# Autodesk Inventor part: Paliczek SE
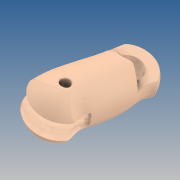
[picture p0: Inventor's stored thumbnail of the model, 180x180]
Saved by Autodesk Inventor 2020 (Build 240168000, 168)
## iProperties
Created: 2019-10
Part Number: Paliczek SE
Material: GFRP
Document SubType Name: Modeling
Designer: yello
Density: 1.75 g/cm^3
Appearance: Default
Author: yello
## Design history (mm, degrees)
feature "Paliczek SE"
sketch "Sketch1"
  geometry: C1 r 2 at (0, 0); 1 further point
  constraints: 1 centre point
  dimensions: "d0" = 4 diameter of C1
extrude "Extrusion1" cut sketch "Sketch1" stored distance "d1" = 100; taper "d2" = 0 deg
sketch "Sketch2"
  geometry: C1 r 5 at (0, 0); 1 further point
  constraints: 1 centre point
  dimensions: "d3" = 10 diameter of C1
extrude "Extrusion2" cut sketch "Sketch2" distance "d4" = 8; taper "d5" = 0 deg
body "Solid1"
